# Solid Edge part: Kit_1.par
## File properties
Sűrűség: 0,000 kg/m^3
Pontosság: 0,990
Author: ahadarics
Last saved by: ahadarics
Revision: 76
Username: ahadarics
Dokumentum tartalom típus: 0
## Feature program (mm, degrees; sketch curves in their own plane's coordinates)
base feature "unnamed BaseFeature 1"
thread "unnamed Thread 1"
chamfer "unnamed Chamfer 1"
sketch for "Furat_1" plane through (0, -49.25, 13.5) normal (0, 0, 1) x-axis (0, 1, 0)
  hole centre (0.25, 0) bore radius 4.283
hole "Furat_1" nominal diameter 9.728 finite  ThreadDepth = 7.5 mm
chamfer "Letörés_2" setback 0.7
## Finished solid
Body 1: solid body, 77 faces, 168 edges, 93 vertices, 1 internal void.
  Faces by surface: plane 39, cylinder 19, torus 11, cone 8
  Edges by curve: line 76, circle 58, intersection 16, spline 12, ellipse 6
Bounding box of the edges (mm; curved faces can reach further): 30.000 x 39.500 x 28.500, from (-15, -79, -15) to (15, -39.5, 13.5).
Cylindrical faces by radius (mm): R4.28 x1, R4.283 x1, R5.25 x8, R7 x1, R7.05 x1, R8.05 x1, R8.1 x1, R9.85 x1, R11 x2, R13.5 x1, R15 x1
Conical faces (half-angle, radius in mm at the cone's reference point): 0.1788 deg R6.7706 x1, 15 deg R8.05 x1, 21.5244 deg R6.2703 x1, 45 deg R4.983 x1, 45 deg R7.15 x1, 45 deg R7.7 x1, 45 deg R11 x1, 60 deg R10.425 x1
Toroidal faces (ring radius, tube radius in mm): R5.3 r0.3 x6, R6.6424 r0.4 x1, R6.85 r0.2 x1, R7.85 r0.2 x1, R7.9 r0.2 x2
Planar faces by outward normal: +x 3, +y 11, +z 2, -x 3, -y 6, oblique 14
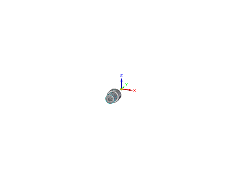
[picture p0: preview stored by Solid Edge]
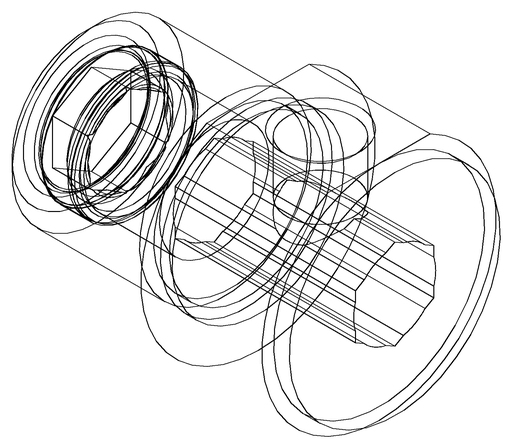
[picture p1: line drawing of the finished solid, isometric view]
